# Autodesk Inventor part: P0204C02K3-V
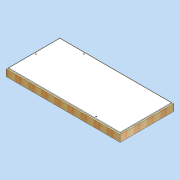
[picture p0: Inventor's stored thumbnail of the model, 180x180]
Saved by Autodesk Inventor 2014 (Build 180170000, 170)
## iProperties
Created: 2011-04
Part Number: P0204C02K3-V
Document SubType Name: Modeling
Designer: david.appleford
Density: 0.253393 g/cm^3
Description: 0.5w x 1w 02 Ceiling Panel - 3 Locks
Mass: 13000 g
Surface Area: 15239.1 cm^2
Volume: 51303.7 cm^3
Cost Center: £59.00
Material: Generic
Appearance: Wood (Pine)
Justset: False
Title: 0.5w x 1w 02 Ceiling Panel - 3 Locks
Author: david.appleford
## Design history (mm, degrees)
sketch "Sketch1"
  geometry: L1 (0, 0)-(1220, 0); L2 (1220, 0)-(1220, 610); L3 (1220, 610)-(0, 610); L4 (0, 610)-(0, 0); L5 (34, 576)-(1186, 576); L6 (1186, 576)-(1186, 34); L7 (1186, 34)-(34, 34); L8 (34, 34)-(34, 576)
  constraints: 16 end point, 4 parallel, 2 perpendicular, 1 horizontal, 3 other
  dimensions: "d0" = 1220 distance between parallel lines of L2 L4 (= w); "d1" = 610 distance between parallel lines of L1 L3 (= 0.5 x w); "d2" = 34 distance between parallel lines of L5 L3 (= 0.5 x t)
extrude "Extrusion1" new body sketch "Sketch1" distance "d3" = 68 (= t); taper "d4" = 0 deg
sketch "Sketch2"
  geometry: L1 (1186, 576)-(1186, 34) reference; L2 (34, 576)-(1186, 576) reference; L3 (34, 34)-(34, 576) reference; L4 (1186, 34)-(34, 34) reference; L5 (1176, 566)-(1176, 44); L6 (1176, 44)-(44, 44); L7 (44, 44)-(44, 566); L8 (44, 566)-(1176, 566); 1 further point
  constraints: 8 end point, 3 other
  dimensions: "d5" = 10 distance between parallel lines of L8 L2
extrude "Extrusion2" join sketch "Sketch2" distance "d6" = 9; taper "d7" = 0 deg
sketch "Sketch3"
  geometry: L1 (-44, 566)-(-1176, 566) reference; L2 (-1176, 566)-(-1176, 44) reference; L3 (-44, 44)-(-44, 566) reference; L4 (-1176, 44)-(-44, 44) reference; 1 further point
extrude "Extrusion3" join sketch "Sketch3" distance "d8" = 6 (= sw); taper "d9" = 0 deg
sketch "Sketch4"
  geometry: L1 (34, 576)-(1186, 576) reference; L2 (1186, 576)-(1186, 34) reference; L3 (1186, 34)-(34, 34) reference; L4 (34, 34)-(34, 576) reference; 4 further points
  dimensions: "d10" = 28 distance from line of point (305, 548) L1 (= k); "d12" = 28 distance from line of L3 point (915, 62) (= k); "d13" = 28 distance from line of point (62, 305) L4 (= k); "d14" = 305 horizontal distance of point (305, 548) point (0, 0) (= 0.25 x w); "d15" = 610 horizontal distance of point (915, 62) point (305, 548) (= 0.5 x w); "d16" = 305 vertical distance of point (62, 305) point (0, 0) (= 0.25 x w)
hole "Hole1" sketch "Sketch4" at (305, 548), (62, 305), (915, 62) diameter "d22" = 12 (= hd); stored, may be unused: countersink angle "d26" = 90 deg, drill point angle "d28" = 118 deg; dims "d23" = 6, "d24" = 4, "d25" = 2, "d27" = 8
chamfer "Chamfer1" distance "d29" = 3; stored, may be unused: second distance "d30" = 2, angle "d31" = 45 deg
body "Solid1"
node "Projected Loop1"
other parameters: "w" = 1220 [user parameter; used in 5 equation terms], "t" = 68 [user parameter; used in 2 equation terms], "e" = 16 [user parameter], "sw" = 6 [user parameter; used in 1 equation term], "sc" = 9 [user parameter], "sf" = 12 [user parameter], "k" = 28 [user parameter; used in 3 equation terms], "hd" = 12 [user parameter; used in 1 equation term]
